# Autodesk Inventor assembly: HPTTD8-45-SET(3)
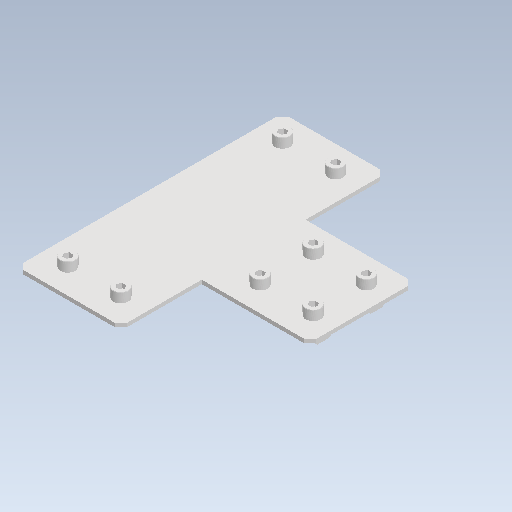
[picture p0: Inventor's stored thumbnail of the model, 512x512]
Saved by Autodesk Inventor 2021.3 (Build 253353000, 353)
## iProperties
Created: 2022-02
Part Number: HPTTD8-45-SET(3)
Document SubType Name: Assembly
Designer: kengo
Author: kengo
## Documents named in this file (4)
- C:\Users\kengo\Documents\S2S_frame\SDC345\frame_misumi_ver12\HPTTD8-45-SET(3).iam
- C:\Users\kengo\Documents\S2S_frame\SDC345\frame_misumi_ver12\HPTTD8-45.ipt
- C:\Users\kengo\Documents\S2S_frame\SDC345\frame_misumi_ver12\HNTT8-8.ipt
- C:\Users\kengo\Documents\S2S_frame\SDC345\frame_misumi_ver12\CBM8-15.ipt
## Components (17 placed, 3 different names)
1. HPTTD8-45
2. HNTT8-8
3. CBM8-15
4. HNTT8-8:1
5. CBM8-15:1
6. HNTT8-8:2
7. CBM8-15:2
8. HNTT8-8:3
9. CBM8-15:3
10. HNTT8-8:4
11. CBM8-15:4
12. HNTT8-8:5
13. CBM8-15:5
14. HNTT8-8:6
15. CBM8-15:6
16. HNTT8-8:7
17. CBM8-15:7
